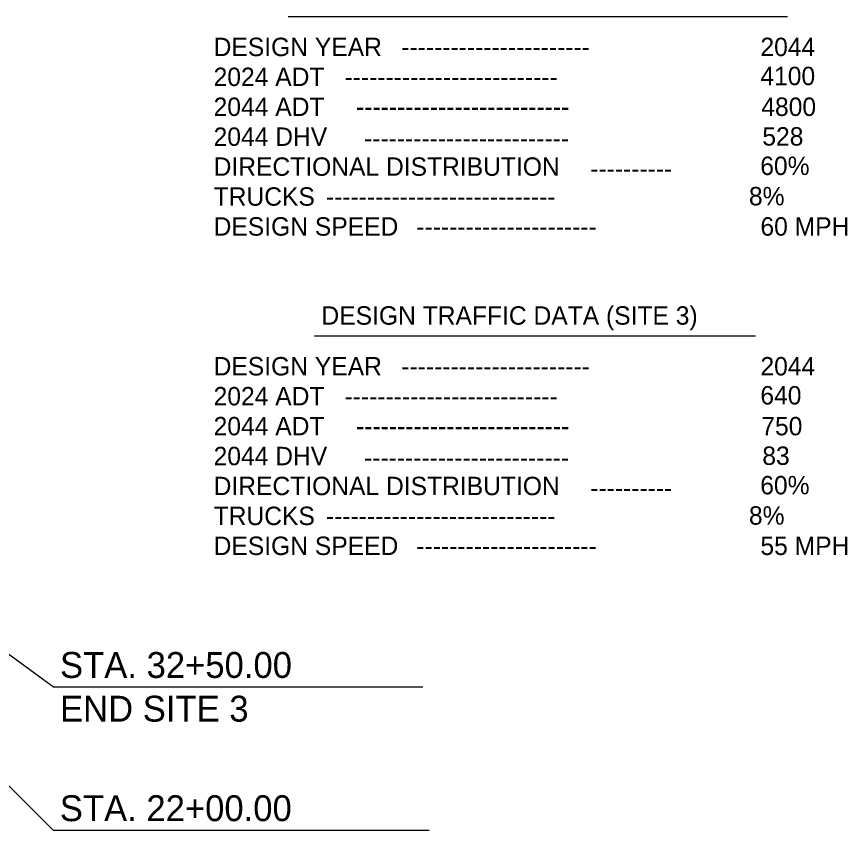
# Model space of a CAD drawing. Extents: x 982240 to 1103002, y 974866 to 1054902.
# Drawn here: x 1070096 to 1096083, y 992513 to 1017967 of the extents above; entities that cross this region are included whole.
import ezdxf

# ---------------------------------------------------------------- set-up
doc = ezdxf.new("R2010")
doc.units = 0
doc.layers.add('R_Draft', color=7, linetype='Continuous')

msp = doc.modelspace()

# ---------------------------------------------------------------- linework, layer by layer
at = {"layer": 'R_Draft'}
for p, q in [((1078590, 1017967), (1094211, 1017967)), ((1079413, 1007979), (1093211, 1007979)), ((1071250, 996988), (1057667, 1006974)), ((1071250, 992513), (1057678, 1005924)), ((1082806, 996988), (1071250, 996988)), ((1082996, 992513), (1071250, 992513))]:
    msp.add_line(p, q, dxfattribs=at)

# ---------------------------------------------------------------- texts
for s, height, p in [('DESIGN YEAR', 576, (1076258, 1016732)), ('2044', 576, (1093363, 1016732)), ('-----------------------', 576, (1082129, 1016732)), ('2024 ADT', 576, (1076258, 1015796)), ('4100', 576, (1093361, 1015823)), (' --------------------------', 576, (1080138, 1015796)), ('2044 ADT', 576, (1076258, 1014860)), ('4800', 576, (1093390, 1014860)), ('--------------------------', 576, (1080714, 1014860)), ('2044 DHV', 576, (1076258, 1013924)), ('528', 576, (1093422, 1013933)), ('-------------------------', 576, (1080964, 1013876)), ('DIRECTIONAL DISTRIBUTION', 576, (1076258, 1012988)), ('60%', 576, (1093357, 1013013)), ('----------', 576, (1088039, 1012924)), ('TRUCKS', 576, (1076258, 1012052)), (' 8%', 576, (1092789, 1012064)), ('----------------------------', 576, (1079770, 1012052)), ('DESIGN SPEED', 576, (1076258, 1011116)), ('60 MPH', 576, (1093363, 1011116)), ('----------------------', 576, (1082601, 1011116)), ('DESIGN TRAFFIC DATA (SITE 3)', 576, (1079631, 1008331)), ('DESIGN YEAR', 576, (1076258, 1006743)), ('2044', 576, (1093363, 1006743)), ('-----------------------', 576, (1082129, 1006743)), ('2024 ADT', 576, (1076258, 1005807)), ('640', 576, (1093361, 1005835)), (' --------------------------', 576, (1080138, 1005807)), ('2044 ADT', 576, (1076258, 1004871)), ('750', 576, (1093390, 1004871)), ('--------------------------', 576, (1080714, 1004871)), ('2044 DHV', 576, (1076258, 1003935)), ('83', 576, (1093422, 1003945)), ('-------------------------', 576, (1080964, 1003887)), ('DIRECTIONAL DISTRIBUTION', 576, (1076258, 1002999)), ('60%', 576, (1093357, 1003024)), ('----------', 576, (1088039, 1002935)), ('TRUCKS', 576, (1076258, 1002063)), (' 8%', 576, (1092789, 1002076)), ('----------------------------', 576, (1079770, 1002063)), ('DESIGN SPEED', 576, (1076258, 1001127)), ('55 MPH', 576, (1093363, 1001127)), ('----------------------', 576, (1082601, 1001127)), ('STA. 32+50.00', 810, (1071453, 997282)), ('END SITE 3', 810, (1071453, 995915)), ('STA. 22+00.00', 810, (1071447, 992802))]:
    msp.add_text(s, height=height, dxfattribs=at).set_placement(p)

doc.saveas('drawing.dxf')
